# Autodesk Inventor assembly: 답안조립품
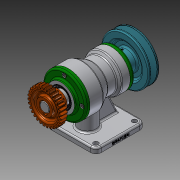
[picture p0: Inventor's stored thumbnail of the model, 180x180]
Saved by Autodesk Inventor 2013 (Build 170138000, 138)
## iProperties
Created: 2019-01
Part Number: 답안조립품
Document SubType Name: Assembly
Designer: hana-cad23
Author: hana-cad23
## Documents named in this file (15)
- C:\Documents and Settings\hana-cad23\바탕 화면\490107V1020\답안조립품.iam
- C:\Documents and Settings\hana-cad23\바탕 화면\490107V1020\본체.ipt
- C:\Documents and Settings\hana-cad23\바탕 화면\490107V1020\베어링 6203.ipt
- C:\Documents and Settings\hana-cad23\바탕 화면\490107V1020\베어링 6205.ipt
- C:\Documents and Settings\hana-cad23\바탕 화면\490107V1020\축.ipt
- C:\Documents and Settings\hana-cad23\바탕 화면\490107V1020\앞커버.ipt
- C:\Documents and Settings\hana-cad23\바탕 화면\490107V1020\뒤커버.ipt
- C:\Documents and Settings\hana-cad23\바탕 화면\490107V1020\오일 실 25 38 8.ipt
- C:\Documents and Settings\hana-cad23\바탕 화면\490107V1020\오일 실 17 30 8.ipt
- C:\Documents and Settings\hana-cad23\바탕 화면\490107V1020\볼트 M4.ipt
- C:\Documents and Settings\hana-cad23\바탕 화면\490107V1020\키 6 x 6 x 18.ipt
- C:\Documents and Settings\hana-cad23\바탕 화면\490107V1020\키 5 x 5 x 20.ipt
- C:\Documents and Settings\hana-cad23\바탕 화면\490107V1020\스퍼기어.ipt
- C:\Documents and Settings\hana-cad23\바탕 화면\490107V1020\V-벨트풀리.ipt
- C:\Documents and Settings\hana-cad23\바탕 화면\490107V1020\멈춤나사 M3.ipt
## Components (1 placed, 1 different names)
1. V-벨트풀리:1 — 각도:4
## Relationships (1: Angle 1)
- 각도:4 [Angle]: V-벨트풀리:1
